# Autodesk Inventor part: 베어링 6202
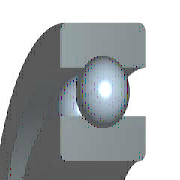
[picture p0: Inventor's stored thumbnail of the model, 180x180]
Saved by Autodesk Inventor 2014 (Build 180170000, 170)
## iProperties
Created: 2009-02
Part Number: 베어링 6202
Material: 강, 연강
Description: 깊은 그루브 볼 베어링
Document SubType Name: Modeling
Standard: KS B 2023
Designer: KYOUNG IL JANG
Standards Organization: KS
Language: ko-KR
Size Designation: 6202 - 15 x 35 x 11
Categories: <MemberInstance><Categories><Category DisplayName="샤프트 부품" InternalName="7f7aeb1f-a693-4053-b835-cee3144e0d98" Mnemonic="SHFT"><Category DisplayName="베어링" Inter
Density: 7.86 g/cm^3
Mass: 45.8725 g
Surface Area: 51.5584 cm^2
Volume: 5.83619 cm^3
Vendor: CBT Solutions
Appearance: 강철
Company: 한국ATC센터
IsCustomPart: 1
Author: KYOUNG IL JANG
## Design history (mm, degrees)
sketch "스케치" dims "d0" = 5.2 (= -0.26 x WD + 0.26 x BD)
  geometry: L1 (2.9, 12.5)-(8.1, 12.5); L2 (5.5, 12.5)-(5.5, 9.9); L3 (5.5, 12.5)-(5.5, 15.1); L4 (3.568, 10.76)-(0, 10.76); L5 (0, 7.5)-(11, 7.5); L6 (3.568, 14.24)-(0, 14.24); L7 (0, 17.5)-(11, 17.5); L8 (11, 7.5)-(11, 10.76); L9 (7.432, 10.76)-(11, 10.76); L10 (7.432, 14.24)-(11, 14.24); L11 (11, 17.5)-(11, 14.24); L12 (-1.4, 0)-(8.4, 0) reference; L13 (0, -0.3)-(0, 5.3) reference
  constraints: 22 end point, 4 point on line, 2 collinear, 2 perpendicular, 2 symmetric about line, 1 midpoint, 1 parallel, 14 other
  dimensions: "d9" = 15 diameter of L5 L12 (= WD); "d11" = 35 diameter of L7 L12 (= BD); "d12" = 11 distance between parallel lines of L8 L13 (= KB); "d13" = 21.52 diameter of L9 L12 (= 0.326 x BD + 0.674 x WD)
revolve "본체" stored, may be unused: angle "d6" = 90 deg
revolve "볼" stored, may be unused: angle "d7" = 90 deg
pattern_circular "IDS_ARRAYBALL[SIMPL:T]" dims angle "d3" = 360 deg
body "Solid1"
fillet "모깎기1" dims "d1" = 0.6 (= KRS)
other parameters: "WD" = 15 [user parameter; used in 5 equation terms], "BD" = 35 [user parameter; used in 5 equation terms], "KB" = 11 [user parameter; used in 1 equation term], "KRS" = 0.6 [user parameter; used in 1 equation term], "d4" = 0, "d5" = 0, "d8" = 0, "d14" = 0, "d15" = 0, "BBA" = 0 [user parameter], "BC0" = 3750000 [user parameter], "BC" = 7800000 [user parameter], "BR" = 17.5 (= 0.5 x BD) [user parameter], "WR" = 7.5 (= 0.5 x WD) [user parameter]
